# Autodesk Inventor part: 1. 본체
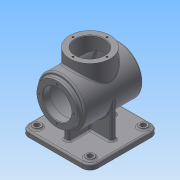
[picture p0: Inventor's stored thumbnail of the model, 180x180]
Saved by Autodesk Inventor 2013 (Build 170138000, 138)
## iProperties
Created: 2015-07
Part Number: 1. 본체
Material: 일반
Document SubType Name: Modeling
Designer: Administrator
Density: 1 g/cm^3
Author: Administrator
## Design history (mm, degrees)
sketch "스케치1"
  geometry: C1 r 45 at (0, 0); 1 further point
  constraints: 1 centre point, 1 coincident
  dimensions: "d0" = 90 diameter of C1
extrude "돌출1" new body sketch "스케치1" distance "d2" = 110; taper "d3" = 0 deg
sketch "스케치2"
  geometry: C1 r 45 at (0, 0) reference; C2 r 38 at (0, 0); 1 further point
  constraints: 1 centre point, 1 coincident
  dimensions: "d4" = 76 diameter of C2
extrude "돌출2" join sketch "스케치2" distance "d6" = 7; taper "d7" = 0 deg
node "작업점1"
  node "작업 평면1"
  node "작업 평면2"
sketch "스케치3"
  geometry: C1 r 38 at (0, 55); 2 further points
  constraints: 1 centre point, 1 coincident
  dimensions: "d9" = 76 diameter of C1
extrude "돌출3" join sketch "스케치3" stored distance "d11" = 7; taper "d12" = 0 deg
sketch "스케치4"
  geometry: C1 r 38 at (0, 0) reference; C2 r 27 at (0, 0); 1 further point
  constraints: 1 centre point, 1 coincident
  dimensions: "d13" = 54 diameter of C2
extrude "돌출4" cut sketch "스케치4" distance "d15" = 62; taper "d16" = 0 deg
node "작업 평면3"
sketch "스케치5"
  geometry: L1 (-38, 24.104)-(-38, 62) reference; L2 (-38, 62)-(-27, 62) reference; L3 (-27, 62)-(-27, 0) reference; L4 (-27, 0)-(27, 0) reference; L5 (27, 0)-(27, 62) reference; L6 (27, 62)-(38, 62) reference; L7 (38, 62)-(38, 24.104) reference; L8 (-65, -68)-(65, -68); L9 (65, -68)-(65, -78); L10 (65, -78)-(-65, -78); L11 (-65, -78)-(-65, -68); A1 r 45 centre (0, 0) between (-38, 24.104) and (38, 24.104) reference; 3 further points
  constraints: 8 end point, 2 parallel, 1 horizontal, 1 midpoint, 1 perpendicular, 1 point on circle, 1 vertical alignment
  dimensions: "d18" = 130 distance of L9.end L10.end; "d20" = 10 distance of L8.end L9.end; "d21" = 140 distance between parallel lines of L10 L6
extrude "돌출5" join sketch "스케치5" distance "d22" = 65; taper "d24" = 0 deg; dims "d23" = 65, "d25" = 0
sketch "스케치7"
  geometry: L1 (20, 70)-(110, 70); L2 (110, 70)-(110, 60); L3 (110, 60)-(20, 60); L4 (20, 60)-(20, 70); L5 (130, 0)-(130, 130) reference; L6 (130, 130)-(0, 130) reference; 5 further points
  constraints: 8 end point, 4 midpoint, 2 parallel, 1 horizontal, 1 horizontal alignment, 1 perpendicular, 1 vertical alignment
  dimensions: "d29" = 90 distance of L1.start L1.end; "d31" = 10 distance of L3.end L1.start
extrude "돌출6" join sketch "스케치7" stored distance "d32" = 65; taper "d33" = 0 deg
sketch "스케치8"
  geometry: L1 (20, 60)-(20, 70) reference; L2 (20, 70)-(110, 70) reference; L3 (110, 70)-(110, 60) reference; L4 (110, 60)-(20, 60) reference; L5 (0, 130)-(130, 130) reference; L6 (130, 130)-(130, 0) reference; L7 (130, 0)-(0, 0) reference; L8 (0, 0)-(0, 130) reference; L9 (60, 110)-(70, 110); L10 (70, 110)-(70, 20); L11 (70, 20)-(60, 20); L12 (60, 20)-(60, 110); 5 further points
  constraints: 8 end point, 4 midpoint, 2 parallel, 1 horizontal, 1 horizontal alignment, 1 perpendicular, 1 vertical alignment
  dimensions: "d34" = 90 distance of L9.end L10.end; "d36" = 10 distance of L9.start L9.end
extrude "돌출7" join sketch "스케치8" stored distance "d37" = 65; taper "d38" = 0 deg
sketch "스케치9"
  geometry: L1 (38, 117)-(38, 110) reference; L2 (38, 110)-(45, 110) reference; L3 (45, 110)-(45, 93) reference; L4 (45, 93)-(62, 93) reference; L5 (62, 93)-(62, 82) reference; L6 (62, 82)-(0, 82) reference; L7 (0, 82)-(0, 28) reference; L8 (0, 28)-(62, 28) reference; L9 (62, 28)-(62, 17) reference; L10 (62, 17)-(45, 17) reference; L11 (45, 17)-(45, 0) reference; L12 (45, 0)-(-45, 0) reference; L13 (-45, 0)-(-45, 10) reference; L14 (-45, 10)-(-68, 10) reference; L15 (-68, 10)-(-68, -10) reference; L16 (-68, -10)-(-78, -10) reference; L17 (-78, -10)-(-78, 120) reference; L18 (-78, 120)-(-68, 120) reference; L19 (-68, 120)-(-68, 100) reference; L20 (-68, 100)-(-45, 100) reference; L21 (-45, 100)-(-45, 110) reference; L22 (-45, 110)-(-38, 110) reference; L23 (-38, 110)-(-38, 117) reference; L24 (-38, 117)-(38, 117) reference; L25 (0, 0)-(0, 117); L26 (27, 117)-(27, 103); L27 (27, 103)-(40, 103); L28 (40, 103)-(40, 7); L29 (40, 7)-(0, 7)
  constraints: 10 end point, 2 parallel, 2 perpendicular, 2 point on line, 1 midpoint
  dimensions: "d39" = 80 diameter of L28 L25; "d41" = 7 distance between parallel lines of L12 L29; "d42" = 54 diameter of L26 L25; "d43" = 14 distance of L26.start L26.end
revolve "회전1" sketch "스케치9" stored, may be unused: angle "d44" = 90 deg
fillet "모깎기1" dims "d45" = 3
chamfer "모따기1" distance "d46" = 1; stored, may be unused: second distance "d47" = 2, angle "d48" = 45 deg
fillet "모깎기2" dims "d49" = 15
sketch "스케치10"
  geometry: L1 (115, 115)-(115, 15) reference; L2 (100, 0)-(0, 0) reference; L3 (-15, 15)-(-15, 115) reference; L4 (0, 130)-(100, 130) reference; L5 (45, 20)-(45, 60) reference; L6 (45, 60)-(5, 60) reference; L7 (5, 60)-(5, 70) reference; L8 (5, 70)-(45, 70) reference; L9 (45, 70)-(45, 110) reference; L10 (45, 110)-(55, 110) reference; L11 (55, 110)-(55, 70) reference; L12 (55, 70)-(95, 70) reference; L13 (95, 70)-(95, 60) reference; L14 (95, 60)-(55, 60) reference; L15 (55, 60)-(55, 20) reference; L16 (55, 20)-(45, 20) reference; C1 r 7.5 at (0, 115); C2 r 7.5 at (100, 115); C3 r 7.5 at (0, 15); C4 r 7.5 at (100, 15); A1 r 15 centre (100, 115) between (115, 115) and (100, 130) reference; A2 r 15 centre (100, 15) between (100, 0) and (115, 15) reference; A3 r 15 centre (0, 15) between (-15, 15) and (0, 0) reference; A4 r 15 centre (0, 115) between (0, 130) and (-15, 115) reference; 1 further point
  constraints: 4 centre point, 4 coincident, 3 equal radius
  dimensions: "d50" = 15 diameter of C1
extrude "돌출8" join sketch "스케치10" distance "d52" = 3; taper "d53" = 0 deg
sketch "스케치11"
  geometry: L1 (45, 5)-(45, 45) reference; L2 (45, 45)-(5, 45) reference; L3 (5, 45)-(5, 55) reference; L4 (5, 55)-(45, 55) reference; L5 (45, 55)-(45, 95) reference; L6 (45, 95)-(55, 95) reference; L7 (55, 95)-(55, 55) reference; L8 (55, 55)-(95, 55) reference; L9 (95, 55)-(95, 45) reference; L10 (95, 45)-(55, 45) reference; L11 (55, 45)-(55, 5) reference; L12 (55, 5)-(45, 5) reference; C1 r 7.5 at (0, 0) reference; C2 r 7.5 at (0, 100) reference; C3 r 7.5 at (100, 100) reference; C4 r 7.5 at (100, 0) reference; 5 further points
  constraints: 4 coincident
hole "구멍1" sketch "스케치11" at (0, 100), (100, 100), (100, 0), (0, 0) diameter "d54" = 10; stored, may be unused: countersink angle "d58" = 90 deg, drill point angle "d60" = 118 deg; dims "d55" = 6, "d56" = 4, "d57" = 2, "d59" = 8
sketch "스케치12"
  geometry: C1 r 38 at (0, 0) reference; C2 r 28 at (0, 0) reference; 2 further points
  constraints: 1 vertical alignment
  dimensions: "d61" = 32 distance of point (0, 32) C1.centre
hole "구멍2" sketch "스케치12" at (0, 32) diameter "d62" = 3.459; stored, may be unused: countersink angle "d66" = 90 deg, drill point angle "d68" = 118 deg; dims "d63" = 8, "d64" = 4, "d65" = 2, "d67" = 10
sketch "스케치13"
  geometry: C1 r 38 at (0, 0) reference; C2 r 28 at (0, 0) reference; 2 further points
  constraints: 1 vertical alignment
  dimensions: "d72" = 32 distance of point (0, 0) point (0, 32)
hole "구멍3" sketch "스케치13" at (0, 32) diameter "d73" = 3.459; stored, may be unused: countersink angle "d77" = 90 deg, drill point angle "d79" = 118 deg; dims "d74" = 8, "d75" = 4, "d76" = 2, "d78" = 10
fillet "모깎기3" dims "d83" = 3
fillet "모깎기4" dims "d84" = 3
fillet "모깎기5" dims "d85" = 3
fillet "모깎기6" dims "d86" = 3
fillet "모깎기7" dims "d87" = 3
sketch "스케치14"
  geometry: C1 r 42 at (0, 0) reference; 2 further points
  constraints: 1 coincident, 1 other
feature "엠보싱1" sketch "스케치14" dims "d3" = 0, "d88" = 0.5, "d89" = 0
node "솔리드1"
pattern_circular "원형 패턴1" dims angle "d70" = 360 deg
pattern_circular "원형 패턴2" dims angle "d81" = 360 deg
node "투영된 루프1"
node "투영된 루프2"
node "투영된 루프3"
node "투영된 루프4"
node "투영된 루프5"
node "절단 모서리 투영1"
node "절단 모서리 투영3"
node "절단 모서리 투영4"
node "절단 모서리 투영5"
node "절단 모서리 투영6"
other parameters: "d8" = 62, "d17" = -78
